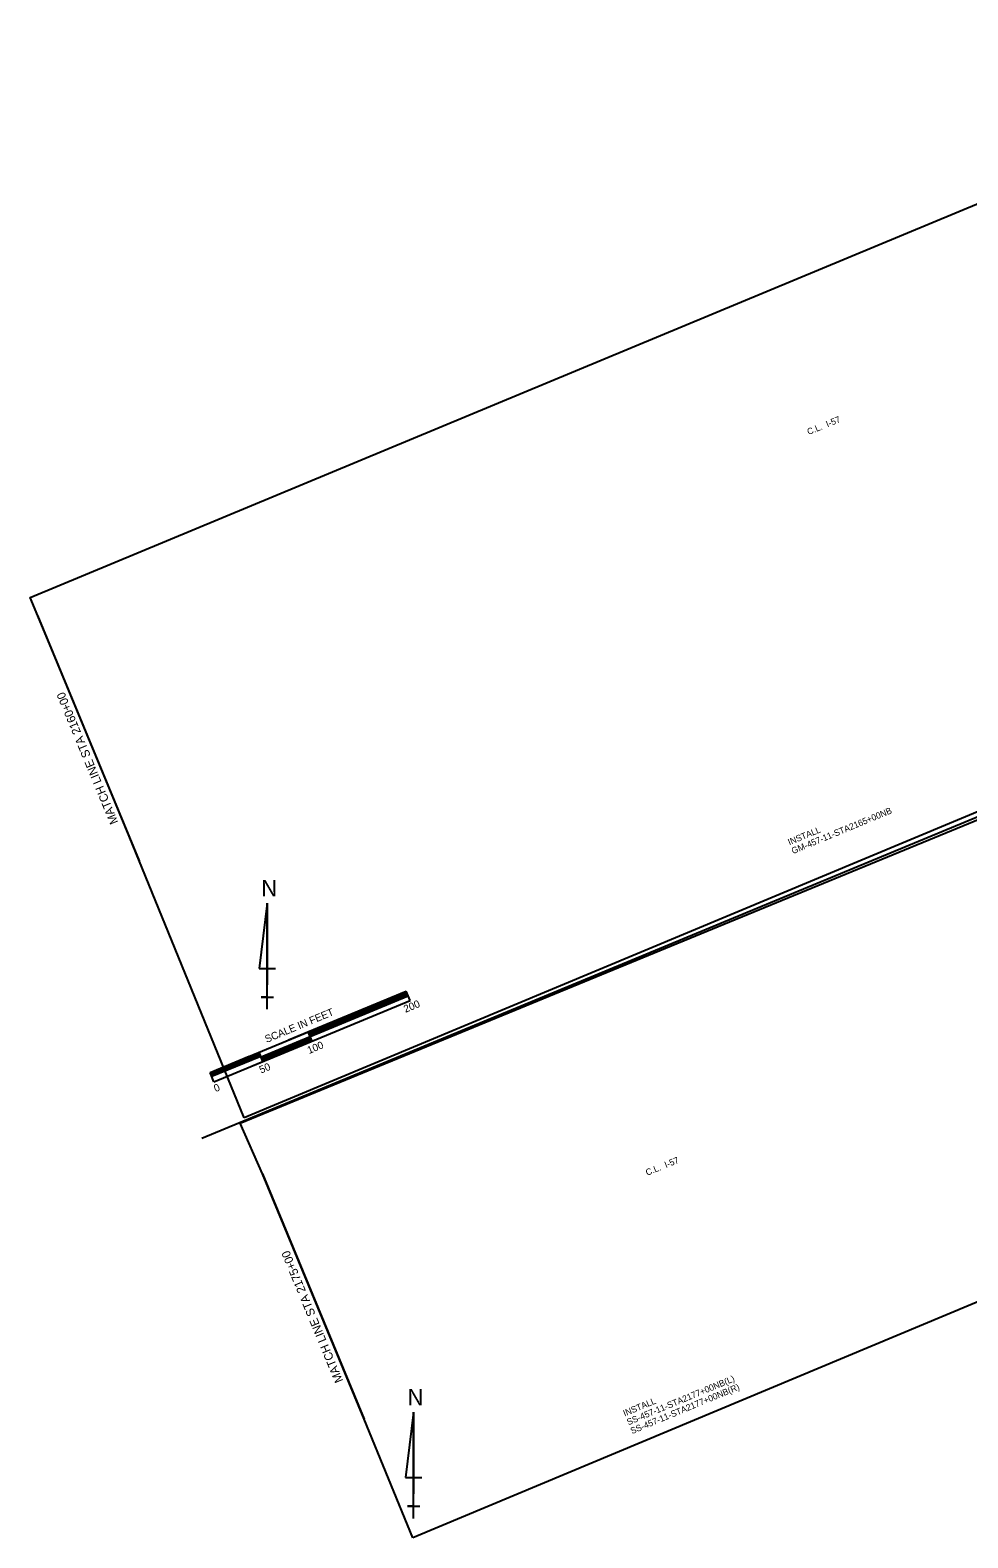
# Model space of a CAD drawing. Extents: x 1721726 to 1723493, y 767411 to 768913.
# Drawn here: x 1721726 to 1722610, y 767411 to 768831 of the extents above; entities that cross this region are included whole.
import ezdxf

# ---------------------------------------------------------------- set-up
doc = ezdxf.new("R2010")
doc.units = 0
for name, color, linetype in [('1', 7, 'Continuous'), ('63', 7, 'Continuous'), ('G-Border-Sheet', 7, 'Continuous'), ('Level 10', 7, 'Continuous'), ('Plan Notes', 7, 'Continuous'), ('R_Annotation', 7, 'Continuous'), ('R_Draft', 7, 'Continuous')]:
    doc.layers.add(name, color=color, linetype=linetype)

msp = doc.modelspace()

# ---------------------------------------------------------------- linework, layer by layer
at = {"layer": '1'}
for points in [[(1721928.1, 767806.8), (1721819.6, 768071.9), (1721743, 768256.7), (1721726.5, 768296.6), (1722805.8, 768744.9), (1722863.6, 768790), (1722985.6, 768789), (1723128.8, 768830.7), (1723205.4, 768645.9), (1722972.5, 768499.4), (1722804.6, 768445.4), (1722817.5, 768356.5), (1722763.1, 768155)], [(1722086.8, 767411.4), (1722041, 767523), (1721945.3, 767754), (1721924.4, 767801.9), (1723089, 768280.7), (1723316.6, 768334.2), (1723410.9, 768157.8), (1723476.5, 767991.7)]]:
    msp.add_lwpolyline(points, close=True, dxfattribs=at)
at = {"layer": '63'}
for p, q in [((1721949.8, 768009), (1721942.2, 767947.5)), ((1721949.8, 767909), (1721949.8, 768009)), ((1721949.8, 768009), (1721949.8, 767932.1)), ((1721942.2, 767947.5), (1721957.5, 767947.5)), ((1721949.8, 767909), (1721949.8, 767932.1)), ((1721949.8, 767920.5), (1721944.1, 767920.5)), ((1721944.1, 767920.5), (1721955.6, 767920.5)), ((1721949.8, 767909), (1721949.8, 767920.5)), ((1722087.7, 767529.7), (1722080, 767468.2)), ((1722087.7, 767429.7), (1722087.7, 767529.7)), ((1722087.7, 767529.7), (1722087.7, 767452.8)), ((1722080, 767468.2), (1722095.4, 767468.2)), ((1722087.7, 767441.3), (1722081.9, 767441.3)), ((1722081.9, 767441.3), (1722093.4, 767441.3)), ((1722087.7, 767429.7), (1722087.7, 767452.8)), ((1722087.7, 767429.7), (1722087.7, 767441.3))]:
    msp.add_line(p, q, dxfattribs=at)
at = {"layer": 'G-Border-Sheet'}
msp.add_line((1721888.2, 767787.7), (1723362.1, 768398.3), dxfattribs=at)
at = {"layer": 'Level 10'}
for p, q in [((1721969.9, 767880.2), (1722080.7, 767926.1)), ((1721988.7, 767887.1), (1722081, 767925.4)), ((1721989, 767886.4), (1722081.3, 767924.6)), ((1721989.3, 767885.6), (1722081.7, 767923.9)), ((1721989.6, 767884.9), (1722082, 767923.1)), ((1721989.9, 767884.1), (1722082.3, 767922.4)), ((1722084.4, 767917.2), (1722080.7, 767926.1)), ((1721896, 767849.6), (1722043.8, 767910.8)), ((1721899.6, 767840.7), (1722084.4, 767917.2)), ((1721990.2, 767883.4), (1722082.6, 767921.7)), ((1721990.2, 767883.4), (1722045.6, 767906.4)), ((1721944, 767864.3), (1721990.2, 767883.4)), ((1721944.3, 767863.5), (1721990.5, 767882.7)), ((1721944.6, 767862.8), (1721990.8, 767881.9)), ((1721944.9, 767862), (1721991.1, 767881.2)), ((1721945.2, 767861.3), (1721991.4, 767880.4)), ((1721945.5, 767860.6), (1721991.7, 767879.7)), ((1721992, 767879), (1721988.4, 767887.8)), ((1721896.3, 767848.8), (1721942.5, 767868)), ((1721896.6, 767848.1), (1721942.8, 767867.2)), ((1721896.9, 767847.3), (1721943.1, 767866.5)), ((1721897.2, 767846.6), (1721943.4, 767865.7)), ((1721936.6, 767856), (1721973.5, 767871.3)), ((1721945.8, 767859.8), (1721942.2, 767868.7)), ((1721896, 767849.6), (1721932.9, 767864.9)), ((1721897.5, 767845.9), (1721943.7, 767865)), ((1721899.6, 767840.7), (1721896, 767849.6))]:
    msp.add_line(p, q, dxfattribs=at)
at = {"layer": 'Plan Notes'}
for p, q in [((1721733.4, 768279.8), (1721829.1, 768048.8)), ((1721945.3, 767754), (1722041, 767523))]:
    msp.add_line(p, q, dxfattribs=at)

# ---------------------------------------------------------------- texts
at = {"layer": '63'}
for p in [(1721944.2, 768015.4), (1722082, 767536.2)]:
    msp.add_text('N', height=15.4, rotation=360, dxfattribs=at).set_placement(p)
at = {"layer": 'Level 10'}
for s, height, p in [('SCALE IN FEET', 7.001, (1721949.3, 767877.3)), ('200', 7, (1722080, 767905.6)), ('100', 7, (1721989.2, 767866.8)), ('50', 7, (1721944, 767848.4)), ('0', 7, (1721901.2, 767830.9))]:
    msp.add_text(s, height=height, rotation=22.5003, dxfattribs=at).set_placement(p)
at = {"layer": 'Plan Notes'}
for s, p in [('MATCH LINE STA 2160+00', (1721809.6, 768085.1)), ('MATCH LINE STA 2175+00', (1722021.4, 767559.3))]:
    msp.add_text(s, height=8, rotation=112.5, dxfattribs=at).set_placement(p)
at = {"layer": 'R_Annotation'}
for s, p in [('GM-457-11-STA2165+00NB', (1722445.1, 768055)), ('INSTALL', (1722441.7, 768063.3)), ('SS-457-11-STA2177+00NB(L)', (1722290, 767517.3)), ('SS-457-11-STA2177+00NB(R)', (1722293.4, 767509)), ('INSTALL', (1722286.5, 767525.6))]:
    msp.add_text(s, height=6, rotation=22.5, dxfattribs=at).set_placement(p)
at = {"layer": 'R_Draft'}
for p in [(1722459.8, 768449.5), (1722307.7, 767752.2)]:
    msp.add_text('C.L.  I-57', height=6, rotation=22.3523, dxfattribs=at).set_placement(p)

doc.saveas('drawing.dxf')
